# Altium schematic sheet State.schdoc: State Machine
size A; Organization: Altium Limited; Address1: L3, 12a Rodborough Rd; Address2: Frenchs Forest; Address3: NSW; Address4: Australia 2086; DocumentNumber: 1; SheetNumber: 1; SheetTotal: 1
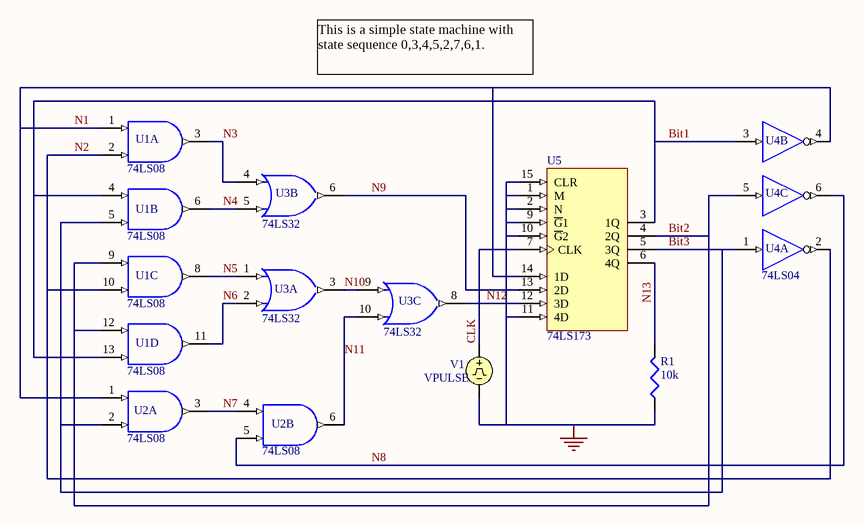
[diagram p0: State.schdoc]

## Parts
R1  10k
U1  74LS08  (parts A,B,C,D of 4)
U2  74LS08  (parts A,B of 4)
U3  74LS32  (parts A,B,C of 4)
U4  74LS04  (parts A,B,C of 6)
U5  74LS173
V1  VPULSE

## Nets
GND: R1.2(BOT) U1.7(GND) U2.7(GND) U3.7(GND) U4.7(GND) U5.1(M) U5.2(N) U5.8(GND) U5.9(~{G}1) U5.10(~{G}2) U5.11(4D) U5.15(CLR) V1.2
VCC: U1.14(VCC) U2.14(VCC) U3.14(VCC) U4.14(VCC) U5.16(VCC)
Bit1: U1.4(A) U1.13(B) U4.3(A) U5.3(1Q)
Bit2: U1.9(A) U1.12(A) U4.5(A) U5.4(2Q)
Bit3: U1.5(B) U2.2(B) U4.1(A) U5.5(3Q)
CLK: U5.7(CLK) V1.1
N1: U1.1(A) U2.1(A) U4.4(Y) U5.14(1D)
N2: U1.2(B) U1.10(B) U4.2(Y)
N3: U1.3(Y) U3.4(A)
N4: U1.6(Y) U3.5(B)
N5: U1.8(Y) U3.1(A)
N6: U1.11(Y) U3.2(B)
N7: U2.3(Y) U2.4(A)
N8: U2.5(B) U4.6(Y)
N9: U3.6(Y) U5.13(2D)
N10: U3.3(Y) U3.9(A)
N11: U2.6(Y) U3.10(B)
N12: U3.8(Y) U5.12(3D)
N13: R1.1(TOP) U5.6(4Q)

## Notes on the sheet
- This is a simple state machine with state sequence 0,3,4,5,2,7,6,1.

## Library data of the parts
R1 = RES: Resistor
U1 U2 = 74LS08: Quad 2-Input Positive-AND Gate
U3 = 74LS32: Quad 2-Input positive-OR Gate
U4 = 74LS04: Hex Inverter
U5 = 74LS173: 4-Bit D-Type Register with 3-State Outputs
V1 = VPULSE: Pulse Voltage Source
